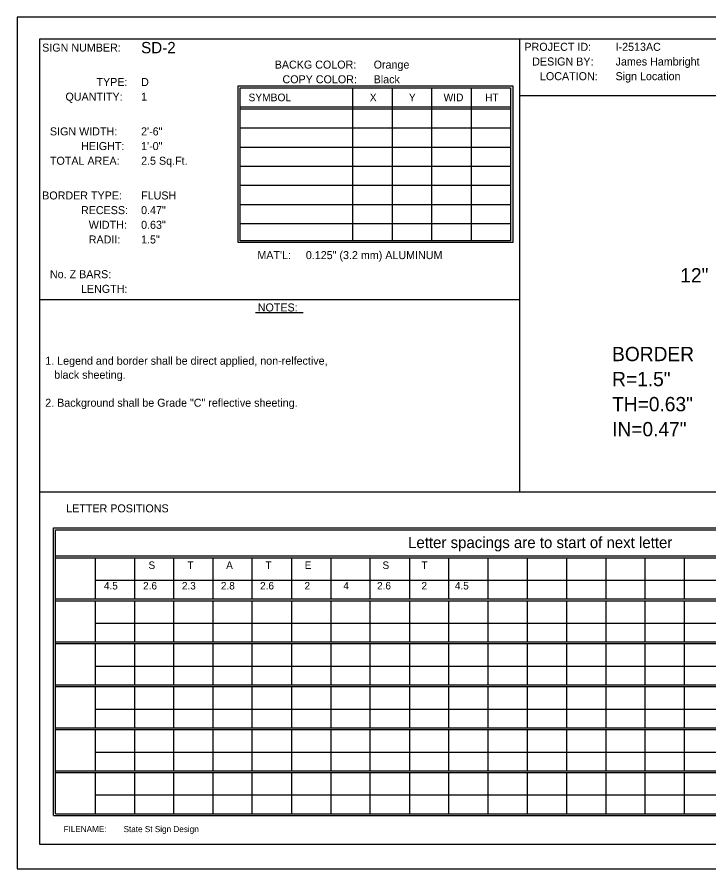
# Model space of a CAD drawing. Extents: x 57.2 to 85.4, y 153.3 to 173.4.
# Drawn here: x 70.51 to 78.56, y 163.43 to 173.35 of the extents above; entities that cross this region are included whole.
import ezdxf

# ---------------------------------------------------------------- set-up
doc = ezdxf.new("R2010")
doc.units = 0
for name, color, linetype in [('Exist Sign D', 7, 'Continuous'), ('GSDIMS', 7, 'Continuous'), ('Old_Level_2', 7, 'Continuous'), ('Old_Level_3', 7, 'Continuous'), ('Old_Level_7', 7, 'Continuous')]:
    doc.layers.add(name, color=color, linetype=linetype)

msp = doc.modelspace()

# ---------------------------------------------------------------- linework, layer by layer
at = {"layer": 'Exist Sign D'}
msp.add_lwpolyline([(85.3839, 173.3509), (70.5057, 173.3509), (70.5057, 163.4285), (85.3839, 163.4285)], close=True, dxfattribs=at)
at = {"layer": 'Old_Level_2'}
for p, q in [((76.3534, 173.0983), (76.3534, 167.8204)), ((74.4102, 172.5257), (74.4102, 170.7452)), ((74.8703, 172.5257), (74.8703, 170.7452)), ((75.3304, 172.5257), (75.3304, 170.7452)), ((75.7905, 172.5257), (75.7905, 170.7452)), ((76.3534, 172.4362), (84.9353, 172.4362)), ((73.1025, 172.3031), (76.2506, 172.3031)), ((73.1025, 172.2811), (76.2506, 172.2811)), ((73.1025, 172.0585), (76.2506, 172.0585)), ((73.1025, 171.836), (76.2506, 171.836)), ((73.1025, 171.6134), (76.2506, 171.6134)), ((73.1025, 171.3908), (76.2506, 171.3908)), ((73.1025, 171.1683), (76.2506, 171.1683)), ((73.1025, 170.9457), (76.2506, 170.9457)), ((76.3534, 170.0581), (70.7723, 170.0581)), ((73.2809, 169.9089), (73.8367, 169.9089)), ((70.7723, 167.8204), (76.3534, 167.8204)), ((76.3534, 167.8204), (84.9353, 167.8204)), ((70.9539, 167.0753), (81.8429, 167.0753)), ((70.9539, 167.0535), (81.8429, 167.0535)), ((71.413, 167.0535), (71.413, 166.5748)), ((71.8722, 167.0535), (71.8722, 166.5748)), ((72.3266, 167.0535), (72.3266, 166.5748)), ((72.7858, 167.0535), (72.7858, 166.5748)), ((73.2402, 167.0535), (73.2402, 166.5748)), ((73.6993, 167.0535), (73.6993, 166.5748)), ((74.1585, 167.0535), (74.1585, 166.5748)), ((74.6129, 167.0535), (74.6129, 166.5748)), ((75.0721, 167.0535), (75.0721, 166.5748)), ((75.5265, 167.0535), (75.5265, 166.5748)), ((75.9856, 167.0535), (75.9856, 166.5748)), ((76.4448, 167.0535), (76.4448, 166.5748)), ((76.8992, 167.0535), (76.8992, 166.5748)), ((77.3583, 167.0535), (77.3583, 166.5748)), ((77.8128, 167.0535), (77.8128, 166.5748)), ((78.2719, 167.0535), (78.2719, 166.5748)), ((71.413, 166.7924), (81.8429, 166.7924)), ((70.9539, 166.5748), (81.8429, 166.5748)), ((70.9539, 166.553), (81.8429, 166.553)), ((71.413, 166.553), (71.413, 166.0743)), ((71.8722, 166.553), (71.8722, 166.0743)), ((72.3266, 166.553), (72.3266, 166.0743)), ((72.7858, 166.553), (72.7858, 166.0743)), ((73.2402, 166.553), (73.2402, 166.0743)), ((73.6993, 166.553), (73.6993, 166.0743)), ((74.1585, 166.553), (74.1585, 166.0743)), ((74.6129, 166.553), (74.6129, 166.0743)), ((75.0721, 166.553), (75.0721, 166.0743)), ((75.5265, 166.553), (75.5265, 166.0743)), ((75.9856, 166.553), (75.9856, 166.0743)), ((76.4448, 166.553), (76.4448, 166.0743)), ((76.8992, 166.553), (76.8992, 166.0743)), ((77.3583, 166.553), (77.3583, 166.0743)), ((77.8128, 166.553), (77.8128, 166.0743)), ((78.2719, 166.553), (78.2719, 166.0743)), ((71.413, 166.2919), (81.8429, 166.2919)), ((70.9539, 166.0743), (81.8429, 166.0743)), ((70.9539, 166.0526), (81.8429, 166.0526)), ((71.413, 166.0526), (71.413, 165.5738)), ((71.8722, 166.0526), (71.8722, 165.5738)), ((72.3266, 166.0526), (72.3266, 165.5738)), ((72.7858, 166.0526), (72.7858, 165.5738)), ((73.2402, 166.0526), (73.2402, 165.5738)), ((73.6993, 166.0526), (73.6993, 165.5738)), ((74.1585, 166.0526), (74.1585, 165.5738)), ((74.6129, 166.0526), (74.6129, 165.5738)), ((75.0721, 166.0526), (75.0721, 165.5738)), ((75.5265, 166.0526), (75.5265, 165.5738)), ((75.9856, 166.0526), (75.9856, 165.5738)), ((76.4448, 166.0526), (76.4448, 165.5738)), ((76.8992, 166.0526), (76.8992, 165.5738)), ((77.3583, 166.0526), (77.3583, 165.5738)), ((77.8128, 166.0526), (77.8128, 165.5738)), ((78.2719, 166.0526), (78.2719, 165.5738)), ((71.413, 165.7914), (81.8429, 165.7914)), ((70.9539, 165.5738), (81.8429, 165.5738)), ((70.9539, 165.5521), (81.8429, 165.5521)), ((71.413, 165.5521), (71.413, 165.0733)), ((71.8722, 165.5521), (71.8722, 165.0733)), ((72.3266, 165.5521), (72.3266, 165.0733)), ((72.7858, 165.5521), (72.7858, 165.0733)), ((73.2402, 165.5521), (73.2402, 165.0733)), ((73.6993, 165.5521), (73.6993, 165.0733)), ((74.1585, 165.5521), (74.1585, 165.0733)), ((74.6129, 165.5521), (74.6129, 165.0733)), ((75.0721, 165.5521), (75.0721, 165.0733)), ((75.5265, 165.5521), (75.5265, 165.0733)), ((75.9856, 165.5521), (75.9856, 165.0733)), ((76.4448, 165.5521), (76.4448, 165.0733)), ((76.8992, 165.5521), (76.8992, 165.0733)), ((77.3583, 165.5521), (77.3583, 165.0733)), ((77.8128, 165.5521), (77.8128, 165.0733)), ((78.2719, 165.5521), (78.2719, 165.0733)), ((71.413, 165.2909), (81.8429, 165.2909)), ((71.413, 165.1291), (71.413, 165.0733)), ((71.8722, 165.1291), (71.8722, 165.0733)), ((72.3266, 165.1291), (72.3266, 165.0733)), ((72.7858, 165.1291), (72.7858, 165.0733)), ((73.2402, 165.1291), (73.2402, 165.0733)), ((73.6993, 165.1291), (73.6993, 165.0733)), ((74.1585, 165.1291), (74.1585, 165.0733)), ((74.6129, 165.1291), (74.6129, 165.0733)), ((75.0721, 165.1291), (75.0721, 165.0733)), ((75.5265, 165.1291), (75.5265, 165.0733)), ((75.9856, 165.1291), (75.9856, 165.0733)), ((76.4448, 165.1291), (76.4448, 165.0733)), ((76.8992, 165.1291), (76.8992, 165.0733)), ((77.3583, 165.1291), (77.3583, 165.0733)), ((77.8128, 165.1291), (77.8128, 165.0733)), ((78.2719, 165.1291), (78.2719, 165.0733)), ((70.9539, 165.0733), (81.8429, 165.0733)), ((70.9539, 165.0733), (81.8429, 165.0733)), ((70.9539, 165.0516), (81.8429, 165.0516)), ((70.9539, 165.0516), (81.8429, 165.0516)), ((71.413, 165.0516), (71.413, 164.6042)), ((71.413, 165.0516), (71.413, 164.5729)), ((71.8722, 165.0516), (71.8722, 164.6042)), ((71.8722, 165.0516), (71.8722, 164.5729)), ((72.3266, 165.0516), (72.3266, 164.6042)), ((72.3266, 165.0516), (72.3266, 164.5729)), ((72.7858, 165.0516), (72.7858, 164.6042)), ((72.7858, 165.0516), (72.7858, 164.5729)), ((73.2402, 165.0516), (73.2402, 164.6042)), ((73.2402, 165.0516), (73.2402, 164.5729)), ((73.6993, 165.0516), (73.6993, 164.6042)), ((73.6993, 165.0516), (73.6993, 164.5729)), ((74.1585, 165.0516), (74.1585, 164.6042)), ((74.1585, 165.0516), (74.1585, 164.5729)), ((74.6129, 165.0516), (74.6129, 164.6042)), ((74.6129, 165.0516), (74.6129, 164.5729)), ((75.0721, 165.0516), (75.0721, 164.6042)), ((75.0721, 165.0516), (75.0721, 164.5729)), ((75.5265, 165.0516), (75.5265, 164.6042)), ((75.5265, 165.0516), (75.5265, 164.5729)), ((75.9856, 165.0516), (75.9856, 164.6042)), ((75.9856, 165.0516), (75.9856, 164.5729)), ((76.4448, 165.0516), (76.4448, 164.6042)), ((76.4448, 165.0516), (76.4448, 164.5729)), ((76.8992, 165.0516), (76.8992, 164.6042)), ((76.8992, 165.0516), (76.8992, 164.5729)), ((77.3583, 165.0516), (77.3583, 164.6042)), ((77.3583, 165.0516), (77.3583, 164.5729)), ((77.8128, 165.0516), (77.8128, 164.6042)), ((77.8128, 165.0516), (77.8128, 164.5729)), ((78.2719, 165.0516), (78.2719, 164.6042)), ((78.2719, 165.0516), (78.2719, 164.5729)), ((71.413, 164.7905), (81.8429, 164.7905)), ((71.413, 164.7905), (81.8429, 164.7905)), ((71.413, 164.6286), (71.413, 164.5729)), ((71.8722, 164.6286), (71.8722, 164.5729)), ((72.3266, 164.6286), (72.3266, 164.5729)), ((72.7858, 164.6286), (72.7858, 164.5729)), ((73.2402, 164.6286), (73.2402, 164.5729)), ((73.6993, 164.6286), (73.6993, 164.5729)), ((74.1585, 164.6286), (74.1585, 164.5729)), ((74.6129, 164.6286), (74.6129, 164.5729)), ((75.0721, 164.6286), (75.0721, 164.5729)), ((75.5265, 164.6286), (75.5265, 164.5729)), ((75.9856, 164.6286), (75.9856, 164.5729)), ((76.4448, 164.6286), (76.4448, 164.5729)), ((76.8992, 164.6286), (76.8992, 164.5729)), ((77.3583, 164.6286), (77.3583, 164.5729)), ((77.8128, 164.6286), (77.8128, 164.5729)), ((78.2719, 164.6286), (78.2719, 164.5729)), ((70.9539, 164.5729), (81.8429, 164.5729)), ((70.9539, 164.5729), (81.8429, 164.5729)), ((70.9539, 164.5511), (81.8429, 164.5511)), ((70.9539, 164.5511), (81.8429, 164.5511)), ((71.413, 164.5511), (71.413, 164.0724)), ((71.413, 164.5511), (71.413, 164.0724)), ((71.8722, 164.5511), (71.8722, 164.0724)), ((71.8722, 164.5511), (71.8722, 164.0724)), ((72.3266, 164.5511), (72.3266, 164.0724)), ((72.3266, 164.5511), (72.3266, 164.0724)), ((72.7858, 164.5511), (72.7858, 164.0724)), ((72.7858, 164.5511), (72.7858, 164.0724)), ((73.2402, 164.5511), (73.2402, 164.0724)), ((73.2402, 164.5511), (73.2402, 164.0724)), ((73.6993, 164.5511), (73.6993, 164.0724)), ((73.6993, 164.5511), (73.6993, 164.0724)), ((74.1585, 164.5511), (74.1585, 164.0724)), ((74.1585, 164.5511), (74.1585, 164.0724)), ((74.6129, 164.5511), (74.6129, 164.0724)), ((74.6129, 164.5511), (74.6129, 164.0724)), ((75.0721, 164.5511), (75.0721, 164.0724)), ((75.0721, 164.5511), (75.0721, 164.0724)), ((75.5265, 164.5511), (75.5265, 164.0724)), ((75.5265, 164.5511), (75.5265, 164.0724)), ((75.9856, 164.5511), (75.9856, 164.0724)), ((75.9856, 164.5511), (75.9856, 164.0724)), ((76.4448, 164.5511), (76.4448, 164.0724)), ((76.4448, 164.5511), (76.4448, 164.0724)), ((76.8992, 164.5511), (76.8992, 164.0724)), ((76.8992, 164.5511), (76.8992, 164.0724)), ((77.3583, 164.5511), (77.3583, 164.0724)), ((77.3583, 164.5511), (77.3583, 164.0724)), ((77.8128, 164.5511), (77.8128, 164.0724)), ((77.8128, 164.5511), (77.8128, 164.0724)), ((78.2719, 164.5511), (78.2719, 164.0724)), ((78.2719, 164.5511), (78.2719, 164.0724)), ((71.413, 164.29), (81.8429, 164.29)), ((71.413, 164.29), (81.8429, 164.29)), ((70.9305, 164.0506), (81.8429, 164.0506)), ((70.9539, 164.0724), (81.8429, 164.0724)), ((70.9539, 164.0724), (81.8429, 164.0724)), ((70.9539, 164.0506), (81.8429, 164.0506))]:
    msp.add_line(p, q, dxfattribs=at)
for points in [[(70.7723, 173.0983), (84.9353, 173.0983), (84.9353, 163.7124), (70.7723, 163.7124)], [(73.0783, 172.5482), (76.2748, 172.5482), (76.2748, 170.7231), (73.0783, 170.7231)], [(73.1025, 172.5257), (76.2506, 172.5257), (76.2506, 170.7452), (73.1025, 170.7452)]]:
    msp.add_lwpolyline(points, close=True, dxfattribs=at)
for points in [[(70.9305, 164.6042), (70.9305, 167.4017), (81.8429, 167.4017)], [(70.9539, 164.6042), (70.9539, 167.3799), (81.8429, 167.3799)], [(70.9305, 164.0506), (70.9305, 165.1291)], [(70.9539, 164.0724), (70.9539, 165.1291)], [(70.9305, 164.1527), (70.9305, 164.6286)], [(70.9539, 164.184), (70.9539, 164.6286)]]:
    msp.add_lwpolyline(points, dxfattribs=at)

# ---------------------------------------------------------------- texts
at = {"layer": 'GSDIMS'}
for s, p in [('12"', (78.2254, 170.2595)), ('BORDER', (77.4317, 169.3428)), ('R=1.5"', (77.4317, 169.0511)), ('TH=0.63"', (77.4317, 168.7594)), ('IN=0.47"', (77.4317, 168.4678))]:
    msp.add_text(s, height=0.16667, dxfattribs=at).set_placement(p)
at = {"layer": 'Old_Level_2'}
for s, height, p in [('PROJECT ID:', 0.093258, (76.4111, 172.9573)), ('I-2513AC', 0.09326, (77.4721, 172.9573)), ('SIGN NUMBER:', 0.093258, (70.7981, 172.9481)), ('DESIGN BY:', 0.09326, (76.5014, 172.7863)), ('James Hambright', 0.093258, (77.4721, 172.7863)), ('BACKG COLOR:', 0.093258, (73.5049, 172.7502)), ('COPY COLOR:', 0.093258, (73.5952, 172.5792)), ('LOCATION:', 0.09326, (76.5918, 172.6153)), ('Sign Location', 0.093258, (77.4721, 172.6153)), ('TYPE:', 0.09326, (71.4306, 172.5476)), ('QUANTITY:', 0.09326, (71.0692, 172.3766)), ('SYMBOL', 0.08903, (73.1994, 172.3701)), ('X', 0.089, (74.6112, 172.3701)), ('Y', 0.089, (75.0665, 172.3701)), ('WID', 0.08903, (75.4699, 172.3701)), ('HT', 0.08903, (75.9528, 172.3701)), ('SIGN WIDTH:', 0.093258, (70.8885, 171.9723)), ('HEIGHT:', 0.09326, (71.2499, 171.8014)), ('TOTAL AREA:', 0.093258, (70.8885, 171.6304)), ('BORDER TYPE:', 0.093258, (70.7981, 171.2263)), ('RECESS:', 0.09326, (71.2499, 171.0553)), ('WIDTH:', 0.09326, (71.3403, 170.8843)), ('RADII:', 0.09326, (71.3403, 170.7134)), ("MAT'L:", 0.09326, (73.303, 170.5314)), ('0.125" (3.2 mm) ALUMINUM', 0.093258, (73.867, 170.5314)), ('No. Z BARS:', 0.093258, (70.8885, 170.3092)), ('LENGTH:', 0.09326, (71.2499, 170.1383)), ('NOTES:', 0.09326, (73.3075, 169.9217)), ('1. Legend and border shall be direct applied, non-relfective, ', 0.093258, (70.8338, 169.3011)), ('   black sheeting.', 0.093258, (70.8338, 169.138)), ('2. Background shall be Grade "C" reflective sheeting.', 0.093258, (70.8338, 168.8119)), ('LETTER POSITIONS', 0.093258, (71.0782, 167.5818)), ('Letter spacings are to start of next letter', 0.130561, (75.0567, 167.1658))]:
    msp.add_text(s, height=height, rotation=360, dxfattribs=at).set_placement(p)
for s, height, p in [('S', 0.087, (72.0362, 166.923)), ('T', 0.087, (72.4901, 166.923)), ('A', 0.087, (72.9396, 166.923)), ('T', 0.087, (73.3978, 166.923)), ('E', 0.087, (73.8538, 166.923)), ('S', 0.087, (74.7594, 166.923)), ('T', 0.087, (75.2133, 166.923)), ('4.5', 0.08704, (71.5167, 166.6836)), ('2.6', 0.08704, (71.9728, 166.6836)), ('2.3', 0.08704, (72.4245, 166.6836)), ('2.8', 0.08704, (72.8783, 166.6836)), ('2.6', 0.08704, (73.3344, 166.6836)), ('2', 0.087, (73.8516, 166.6836)), ('4', 0.087, (74.3033, 166.6836)), ('2.6', 0.08704, (74.696, 166.6836)), ('2', 0.087, (75.2133, 166.6836)), ('4.5', 0.08704, (75.6015, 166.6836))]:
    msp.add_text(s, height=height, dxfattribs=at).set_placement(p)
at = {"layer": 'Old_Level_3'}
for s, height, p in [('SD-2', 0.13212, (71.9495, 172.9286)), ('Orange', 0.09326, (74.6562, 172.7502)), ('Black', 0.09326, (74.6562, 172.5792)), ('D', 0.0933, (71.9495, 172.5476)), ('1', 0.0933, (71.9495, 172.3766)), ('2\'-6"', 0.09326, (71.9495, 171.9723)), ('1\'-0"', 0.09326, (71.9495, 171.8014)), ('2.5 Sq.Ft.', 0.09326, (71.9495, 171.6304)), ('FLUSH', 0.09326, (71.9495, 171.2263)), ('0.47"', 0.09326, (71.9495, 171.0553)), ('0.63"', 0.09326, (71.9495, 170.8843)), ('1.5"', 0.09326, (71.9495, 170.7134))]:
    msp.add_text(s, height=height, rotation=360, dxfattribs=at).set_placement(p)
at = {"layer": 'Old_Level_7'}
for s, height, p in [('FILENAME:', 0.07094, (71.0467, 163.8576)), ('State St Sign Design', 0.070939, (71.7452, 163.8576))]:
    msp.add_text(s, height=height, rotation=360, dxfattribs=at).set_placement(p)

doc.saveas('drawing.dxf')
